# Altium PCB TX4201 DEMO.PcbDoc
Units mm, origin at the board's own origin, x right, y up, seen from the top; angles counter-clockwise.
Board outline 46 x 26 mm, 2 copper layers (Top Layer, Bottom Layer); 14 components, 7 nets, 48 pads, 74 vias.
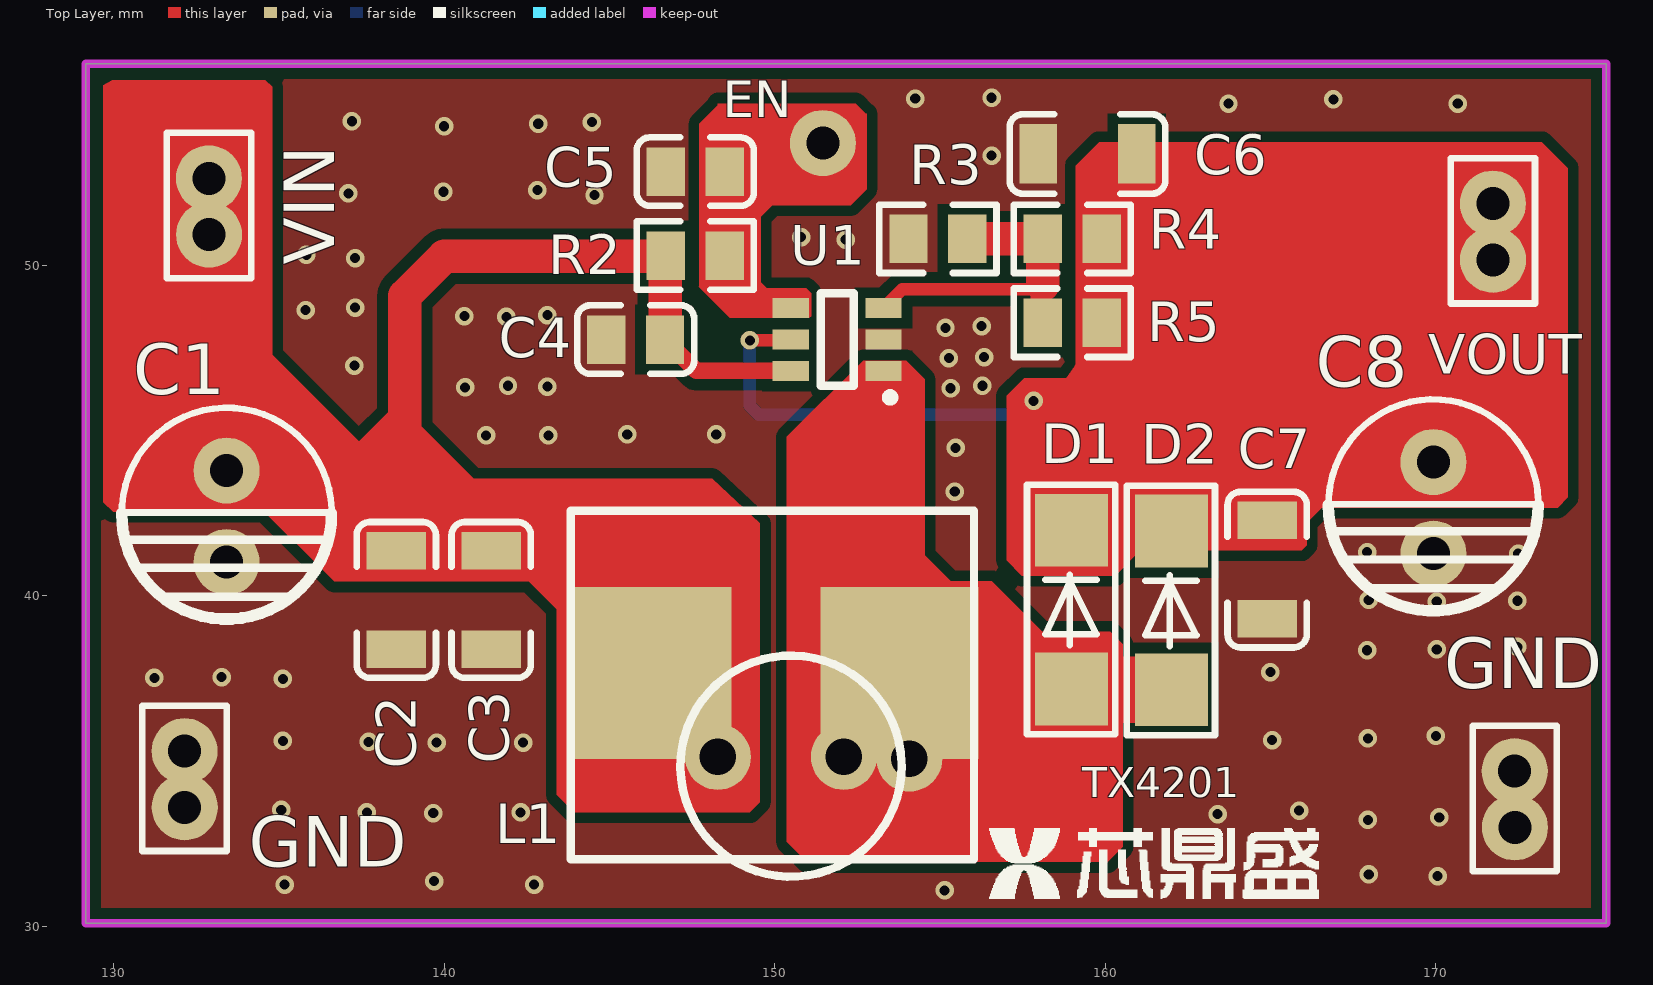
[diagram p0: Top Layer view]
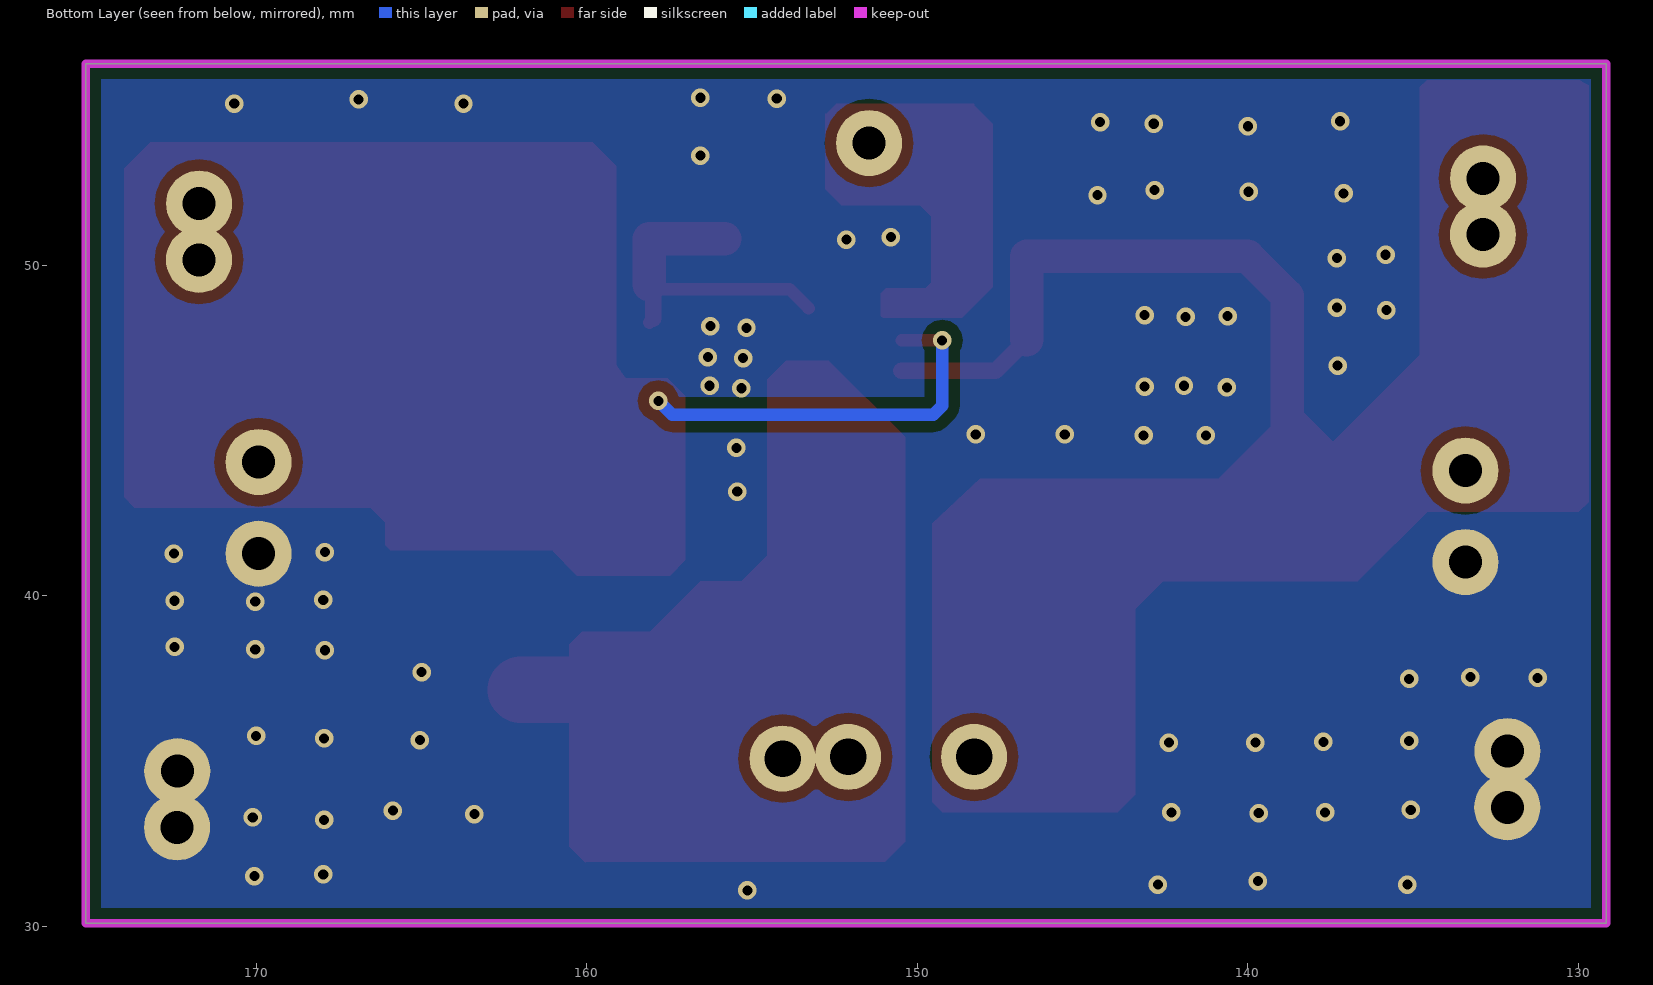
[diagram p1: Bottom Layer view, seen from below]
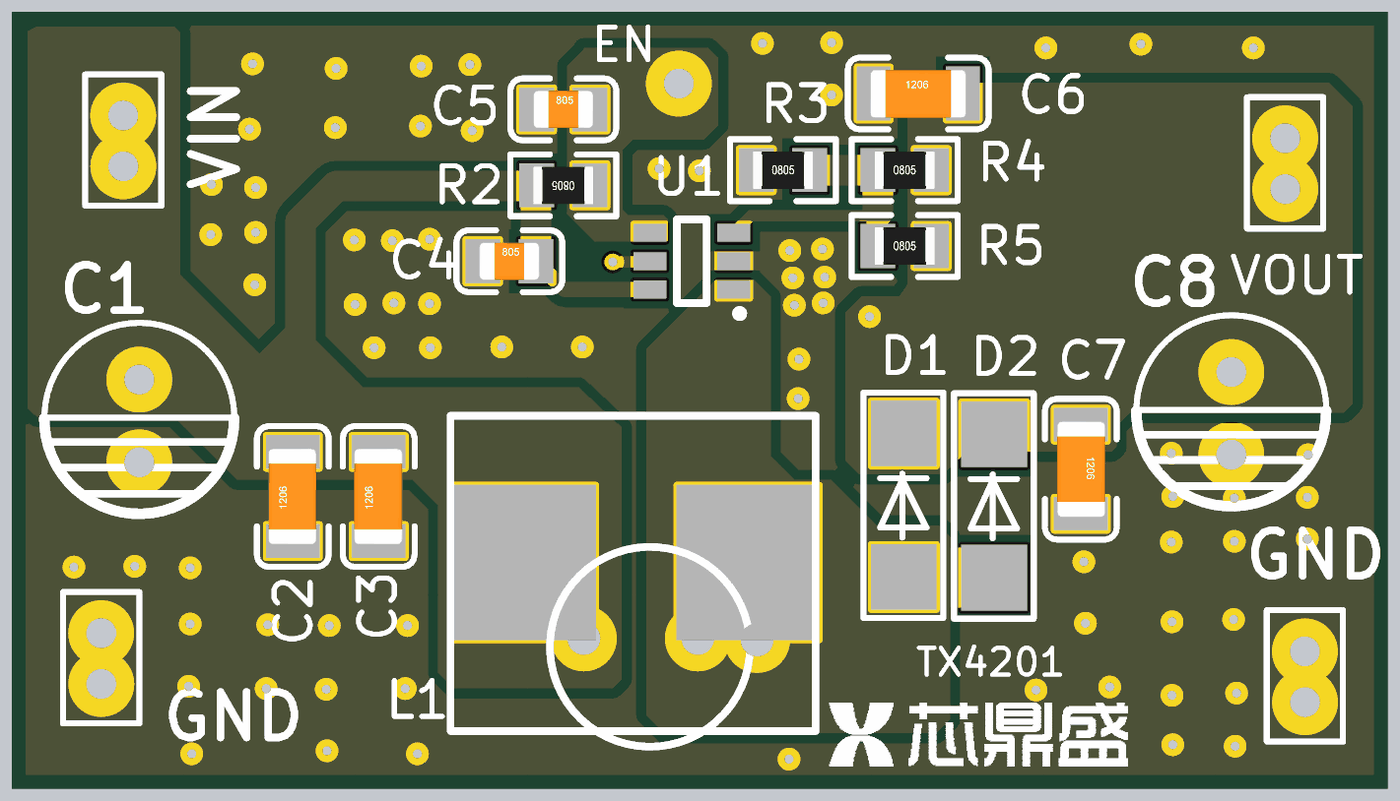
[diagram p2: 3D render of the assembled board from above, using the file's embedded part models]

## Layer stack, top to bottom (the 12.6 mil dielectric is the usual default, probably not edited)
Top Layer: signal copper 0.0356
Dielectric: dielectric 0.32, FR-4, Dk 4.8
Bottom Layer: signal copper 0.0356

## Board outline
129.159,30.099 175.159,30.099 175.159,56.099 129.159,56.099

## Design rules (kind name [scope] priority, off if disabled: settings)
Clearance [All] p1: gap=0.33
PolygonConnect [All] p1: connectstyle=Direct reliefconductorwidth=0.254 reliefentries=4 polygonreliefangle="90 Angle"
RoutingVias [All] p1: holewidth=0.711 width=1.27 viastyle="Through Hole" minholewidth=0.711 minwidth=1.27 maxholewidth=0.711 maxwidth=1.27
SilkscreenOverComponentPads [All] p1: minsilkscreentomaskgap=0.254
SolderMaskExpansion [All] p1: expansion=0.102
TestPointUsage [All] p1: valid=0 allowmultiple=FALSE
Testpoint [All] p1: side=15 testpointundercomponent=TRUE minsize=1.016 maxsize=2.54 preferedsize=1.524 minholesize=0 maxholesize=1.016 preferedholesize=0.813 testpointgrid=0.025 style=1023 order=0-112345678
Width [All] p1: maxlimit=2.54 minlimit=0.381 preferedwidth=0.381
23 further rules are at their usual default settings.

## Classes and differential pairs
component class TX4211: C1 C7 D1 L1 R4 R5 U1

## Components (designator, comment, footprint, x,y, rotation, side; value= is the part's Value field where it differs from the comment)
C2 "2.2uF (225) 10% 50V" 1206_C 138.557,39.878 r270 top (schematic designator C3)
C3 "2.2uF (225) 10% 50V" 1206_C 141.427,39.878 r270 top
C4 "Comment" 0805_C 145.796,47.752 r0 top
C5 "Comment" 0805_C 147.599,52.832 r0 top
C6 "2.2uF (225) 10% 50V" 1206_C 159.461,53.365 r0 top (schematic designator C3)
C7 "2.2uF (225) 10% 50V" 1206_C 164.897,40.792 r90 top (schematic designator C3)
D1 "" PCBComponent_1 158.928,43.18 r90 top
D2 "" PCBComponent_1 161.95,43.155 r90 top (schematic designator D1)
R2 "Comment" 0805_R 147.599,50.292 r180 top
R3 "3.3KΩ (3301) ±1%" 0805_R 154.94,50.8 r0 top (schematic designator R2)
R4 "3.3KΩ (3301) ±1%" 0805_R 159.004,50.8 r0 top (schematic designator R1)
R5 "3.3KΩ (3301) ±1%" 0805_R 159.004,48.26 r0 top (schematic designator R1)
U1 "Component_1" SOT-23-6 151.892,47.752 r0 top
? "Comment" LOGO(10x2)mm 160.02,31.496 r0 top

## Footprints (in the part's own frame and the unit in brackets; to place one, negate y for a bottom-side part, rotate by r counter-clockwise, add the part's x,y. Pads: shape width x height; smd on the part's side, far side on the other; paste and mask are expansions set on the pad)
0805_C [mm]
  rect 1.16x1.47 smd: 1(-0.89,0) 2(0.89,0)
  silkscreen extent -1.77,-1.04 1.77,1.04, body extent -1,-0.62 1,0.63, height 0.77
0805_R [mm]
  rect 1.16x1.47 smd: 1(-0.89,0) 2(0.89,0)
  silkscreen extent -1.77,-1.04 1.77,1.03, body extent -1,-0.62 1,0.63, height 0.49
1206_C [mm]
  rect 1.13x1.8 smd: 1(-1.49,0) 2(1.49,0)
  silkscreen extent -2.36,-1.2 2.35,1.2, body extent -1.6,-0.81 1.6,0.79, height 1
LOGO(10x2)mm [mm]
  silkscreen extent -3.52,-0.65 6.44,1.47
PCBComponent_1 [mm]
  rect 2.2x2.2 smd: 1(-5.994,-0.051) 2(-1.194,-0.051)
  silkscreen extent -7.37,-1.37 0.18,1.3
SOT-23-6 [mm]
  rect 1.1x0.6 smd: 1(1.4,-0.95) 2(1.4,0) 3(1.4,0.95) 4(-1.4,0.95) 5(-1.4,0) 6(-1.4,-0.95)
  silkscreen extent -0.5,-1.87 1.73,1.4

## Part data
C2 C3 C6 C7: library part "1206 2.2uF (225) 10% 50V", "贴片电容"
D1 D2: library part 二极管
R3 R4 R5: library part "0805 3.3KΩ (3301) 1%", "贴片电阻"

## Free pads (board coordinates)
  round 2 hole 1: 1(132.152,35.305) 1(132.156,33.604) 1(132.889,52.628) 1(132.893,50.927) 1(133.426,41.021) 1(133.426,43.79) 1(151.46,53.696) 1(169.926,41.275) 1(169.926,44.044) 1(171.725,51.866) 1(171.729,50.165) 1(172.386,34.696) 1(172.39,32.995)
  rect 4.78x5.2 smd: 1(146.304,37.668) 1(153.772,37.668)
  round 2 hole 1.1: 12(148.285,35.128) 12(152.095,35.128) 12(154.076,35.077)

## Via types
v1: diameter 0.559, hole 0.305, Top Layer to Bottom Layer, 74 vias

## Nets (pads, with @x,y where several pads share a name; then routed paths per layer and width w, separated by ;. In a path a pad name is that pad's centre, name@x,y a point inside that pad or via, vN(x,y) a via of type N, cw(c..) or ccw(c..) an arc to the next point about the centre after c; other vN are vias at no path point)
EN: C5.2 pad.1@151.46,53.696 R2.1 U1.4
FB: R3.2 R4.1 R5.1 U1.3 | length 9.9
  Top Layer w0.381: U1.3 153.866,49.276 157.986,49.276 158.114,49.404 ; R5.1@157.986,48.388 R5.1
  Top Layer w0.5: R5.1@157.986,48.388 157.986,49.276
  Top Layer w1.016: R3.2 R4.1 158.114,49.404
GND: C2.2 C3.2 C4.1 C5.1 C6.1 C7.1 pad.1@132.152,35.305 pad.1@132.156,33.604 pad.1@133.426,41.021 pad.1@169.926,41.275 pad.1@172.39,32.995 pad.1@172.386,34.696 R3.1 U1.2
  other v1: 155.143,31.09 135.179,31.267 142.723,31.267 139.7,31.369 170.053,31.521 167.97,31.572 167.945,33.223 170.104,33.299 163.398,33.401 139.675,33.426 137.668,33.452 142.316,33.452 165.862,33.503 135.077,33.528 139.776,35.56 142.392,35.56 137.719,35.585 135.128,35.611 165.049,35.636 167.945,35.687 170.002,35.763 135.128,37.49 131.242,37.516 133.274,37.541 164.998,37.694 167.919,38.354 170.028,38.379 172.466,38.456 170.028,39.827 172.466,39.853 167.97,39.878 172.491,41.275 167.919,41.326 155.448,43.155 155.473,44.475 141.275,44.856 143.154,44.856 145.542,44.882 148.234,44.882 155.321,46.279 140.64,46.304 143.129,46.33 141.935,46.355 156.286,46.355 137.287,46.965 155.27,47.193 156.337,47.219 155.169,48.108 156.261,48.158 141.884,48.438 140.614,48.463 143.129,48.489 135.814,48.641 137.312,48.717 137.312,50.216 135.839,50.317 152.146,50.775 150.8,50.851 144.551,52.121 137.109,52.172 139.979,52.222 142.824,52.273 156.566,53.315 140.005,54.204 142.85,54.28 144.475,54.331 137.211,54.356 163.728,54.889 170.663,54.889 166.903,55.016 154.254,55.042 156.566,55.067
NC: 
NetC3_2: C6.2 C7.2 D1.2 D2.2 pad.1@169.926,44.044 pad.1@171.725,51.866 pad.1@171.729,50.165 R4.2 R5.2 U1.5 | length 13.7
  Top Layer w0.381: v1(149.25,47.727) U1.5@150.467,47.727 ; v1(157.836,45.898) 158.979,44.755
  Bottom Layer w0.381: v1(149.25,47.727) 149.25,45.745 149.517,45.479 157.417,45.479 v1(157.836,45.898)
SW: D1.1 D2.1 pad.1@153.772,37.668 pad.12@152.095,35.128 pad.12@154.076,35.077 U1.1 | length 3
  Top Layer w2: D1.1@159.004,37.16 D2.1
VDD: C2.1 C3.1 C4.2 pad.1@132.889,52.628 pad.1@132.893,50.927 pad.1@133.426,43.79 pad.1@146.304,37.668 pad.12@148.285,35.128 R2.2 U1.6 | length 20.8
  Top Layer w0.5: C4.2 147.636,46.802 U1.6
  Top Layer w1.016: 138.811,43.409 138.811,49.073 140.007,50.269 146.686,50.269 C4.2

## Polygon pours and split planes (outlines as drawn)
GND on Top Layer "Top Layer-No Net" (solid, remove dead copper, pour order 1000): 129.464,55.677 175.464,55.677 175.464,29.677 129.464,29.677 129.464,55.677
GND on Bottom Layer "Top Layer-No Net" (solid, remove dead copper, pour order 1001): 129.159,55.88 129.429,56.15 175.159,56.15 175.159,30.15 129.159,30.15 129.159,56.15

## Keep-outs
Keep-Out Layer:
  the board outline again, w0.254

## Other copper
Top Layer:
  region net VDD: 136.754,42.164 137.287,42.697 148.107,43.536 149.555,42.189 149.555,33.757 149.25,33.452 143.942,33.452 143.408,33.985 143.408,39.599 142.57,40.437 137.058,40.437 136.754,40.742
  region net VDD: 149.098,42.545 148.107,43.536 138.557,43.536 134.798,47.295 134.798,55.397 134.595,55.601 129.972,55.601 129.794,55.499 129.692,55.448 129.692,42.824 129.997,42.545
  region net VDD: 134.417,42.697 136.677,40.437 137.287,40.437 137.287,42.697
  region net VDD: 139.319,45.11 140.894,43.536 140.894,43.51 139.268,43.51 139.319,43.561
  region net VDD: 136.754,43.993 138.328,45.568 138.328,43.51 137.236,43.51
  region net EN: 147.726,54.28 148.285,54.839 148.285,54.889 152.451,54.889 152.756,54.585 152.781,54.585 152.781,52.299 152.298,51.816 148.133,51.816 147.726,52.222
  region net EN: 147.726,52.248 147.726,49.378 147.701,49.352 148.641,48.412 151.054,48.412 151.105,48.463 151.105,49.149 150.952,49.301 149.758,49.301 149.581,49.479 149.581,51.46 149.962,51.841 149.555,52.248
  region net NetC3_2: 159.106,53.01 159.817,53.721 173.203,53.721 173.99,52.934 173.99,42.977 173.685,42.672 166.548,42.672 166.091,42.215 166.091,41.529 165.938,41.377 161.036,41.377 161.036,41.351 160.299,40.615 157.48,40.615 157.023,41.072 157.023,46.05 157.556,46.584 158.826,46.584 159.08,46.939 159.106,47.015
  region net SW: 152.679,47.117 153.975,47.117 154.534,46.558 154.534,41.224 155.321,40.437 156.566,40.437 158.09,38.913 160.147,38.913 160.528,38.532 160.528,32.41 160.045,31.928 160.02,31.953 150.978,31.953 150.368,32.563 150.368,44.806

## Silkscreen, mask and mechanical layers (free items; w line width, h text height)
Top Overlay:
  lines w0.2: 130.353,42.52 136.576,42.52 ; 130.877,32.283 130.877,36.68 ; 130.886,32.283 133.401,32.283 ; 130.927,36.68 133.427,36.68 133.427,32.283 ; 131.614,49.606 131.614,54.003 ; 131.623,49.606 134.137,49.606 ; 131.664,54.003 134.164,54.003 134.164,49.606 ; 136.601,42.621 ccw(c133.428,42.515) 136.602,42.57 ; 166.853,42.774 173.076,42.774 ; 170.45,48.844 170.45,53.241 ; 170.459,48.844 172.974,48.844 ; 170.5,53.241 173,53.241 173,48.844 ; 171.111,31.674 171.111,36.071 ; 171.12,31.674 173.634,31.674 ; 171.161,36.071 173.661,36.071 173.661,31.674 ; 173.101,42.875 ccw(c169.928,42.769) 173.102,42.824
  lines w0.254: 130.5,41.696 136.5,41.696 ; 130.8,40.846 135.975,40.846 ; 131.575,39.971 135.325,39.971 ; 153.838,34.951 ccw(c150.495,34.849) 153.839,34.875 ; 167,41.95 173,41.95 ; 167.3,41.1 172.475,41.1 ; 168.075,40.225 171.825,40.225 ; 143.832,32.029 143.832,42.579 156.032,42.579 156.032,32.029 143.832,32.029
  lines w0.35: 130.251,42.494 ccw(c133.423,42.469) 136.595,42.494 ; 166.751,42.748 ccw(c169.923,42.723) 173.095,42.748
  text "EN" at 148.438,54.483 h1.1
  text "VIN" at 136.677,50.013 h1.52 r90
  text "VOUT" at 169.774,46.711 h1.2
  text "C8" at 166.37,46.33 h1.52
  text "C1" at 130.607,46.101 h1.52
  text "GND" at 170.256,37.211 h1.52
  text "TX4201" at 159.309,33.909 h0.9
  text "L1" at 141.554,32.512 h1.2
  text "GND" at 134.087,31.801 h1.52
